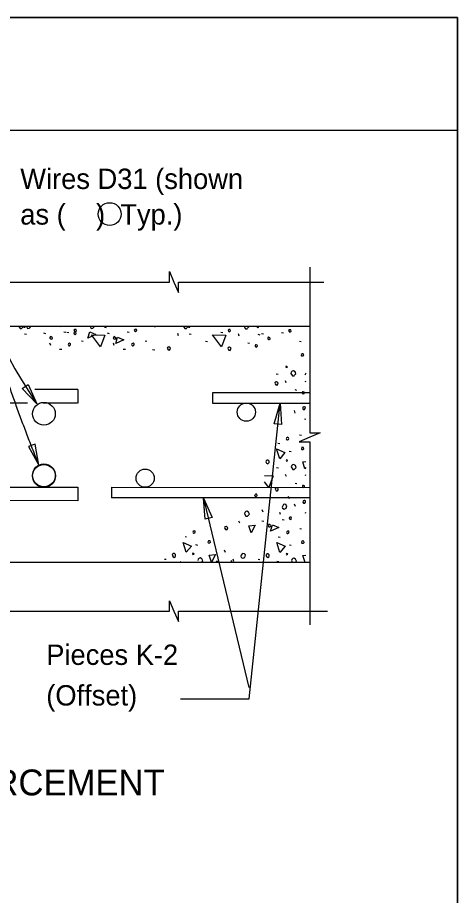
# Model space of a CAD drawing. Extents: x 0 to 20.5, y 0 to 13.
# Drawn here: x 18.352 to 20.525, y 8.632 to 12.973 of the extents above; entities that cross this region are included whole.
import ezdxf

# ---------------------------------------------------------------- set-up
doc = ezdxf.new("R2010")
doc.units = 0
for name, color, linetype in [('ActivePts-ConstElements', 7, 'Continuous'), ('BeamConc', 7, 'Continuous'), ('Dimension', 7, 'Continuous'), ('Miscellaneous', 7, 'Continuous'), ('Miscellaneous1', 7, 'Continuous'), ('Rebar', 7, 'Continuous'), ('Rebar_h', 7, 'Continuous')]:
    doc.layers.add(name, color=color, linetype=linetype)

msp = doc.modelspace()

# ---------------------------------------------------------------- linework, layer by layer
at = {"layer": 'ActivePts-ConstElements'}
msp.add_lwpolyline([(0, 0), (20.5253, 0), (20.5253, 12.9731), (0, 12.9731)], close=True, dxfattribs=at)
at = {"layer": 'BeamConc'}
for p, q in [((19.7956, 11.4449), (16.1478, 11.4449)), ((19.7956, 10.2782), (16.1478, 10.2782))]:
    msp.add_line(p, q, dxfattribs=at)
at = {"layer": 'Dimension'}
for p, q in [((-0.008, 12.4165), (20.5253, 12.4165)), ((19.4966, 9.6606), (19.2748, 10.5821))]:
    msp.add_line(p, q, dxfattribs=at)
for points in [[(19.7956, 11.7379), (19.7956, 10.9199), (19.8473, 10.9199), (19.7956, 10.8974), (19.7439, 10.8749), (19.7956, 10.8749), (19.7956, 9.9704)], [(18.2538, 11.6648), (19.102, 11.6648), (19.102, 11.7165), (19.1245, 11.6648), (19.147, 11.6131), (19.147, 11.6648), (19.8652, 11.6648)], [(19.1573, 9.6044), (19.4966, 9.6044), (19.649, 11.0659)], [(18.1961, 10.0376), (19.102, 10.0376), (19.102, 10.0893), (19.1245, 10.0376), (19.147, 9.986), (19.147, 10.0376), (19.883, 10.0376)]]:
    msp.add_lwpolyline(points, dxfattribs=at)
for points in [[(18.4035, 11.1587), (18.4476, 11.0627), (18.3744, 11.1388)], [(19.6206, 10.9641), (19.649, 11.0659), (19.6557, 10.9605)], [(18.4566, 10.7599), (18.4391, 10.8641), (18.4058, 10.8525)], [(19.2785, 10.4918), (19.2713, 10.5972), (19.3128, 10.5001)]]:
    msp.add_lwpolyline(points, close=True, dxfattribs=at)
for points, degree in [([(18.1627, 11.6549), (18.2484, 11.2789), (18.4566, 10.7599)], 2), ([(18.1631, 11.6533), (18.1786, 11.6093), (18.2222, 11.3932), (18.4476, 11.0627)], 3)]:
    msp.add_open_spline(points, degree=degree, dxfattribs=at)
at = {"layer": 'Miscellaneous'}
for p, q in [((18.5528, 11.4435), (18.5522, 11.4449)), ((18.5687, 11.4423), (18.5677, 11.4449)), ((18.5798, 11.4188), (18.5898, 11.417)), ((18.5957, 11.4176), (18.6058, 11.4158)), ((18.7802, 11.4429), (18.7902, 11.4411)), ((18.8938, 11.4188), (18.9038, 11.417)), ((19.0318, 11.4411), (19.0304, 11.4449)), ((19.3569, 11.4176), (19.3669, 11.4158)), ((18.3866, 11.4093), (18.3961, 11.407)), ((18.4803, 11.4134), (18.4897, 11.4111)), ((18.6676, 11.3746), (18.6765, 11.3728)), ((18.7943, 11.4134), (18.8037, 11.4111)), ((18.9816, 11.3746), (18.9904, 11.3728)), ((19.1478, 11.3993), (19.1437, 11.4105)), ((19.2006, 11.4093), (19.2101, 11.407)), ((19.4475, 11.3981), (19.4433, 11.4093)), ((19.5388, 11.407), (19.5482, 11.4046)), ((19.557, 11.4111), (19.5664, 11.4087)), ((19.6566, 11.4164), (19.6666, 11.4146)), ((18.5156, 11.351), (18.5115, 11.3622)), ((18.5598, 11.3339), (18.5704, 11.3327)), ((18.8296, 11.351), (18.8255, 11.3622)), ((18.8738, 11.3339), (18.8844, 11.3327)), ((19.0188, 11.3315), (19.0294, 11.3304)), ((19.2813, 11.3734), (19.2901, 11.3716)), ((19.4899, 11.3651), (19.4987, 11.3634)), ((19.7444, 11.3722), (19.7532, 11.3704)), ((19.6301, 11.2108), (19.6401, 11.209)), ((19.6796, 11.166), (19.6755, 11.1772)), ((19.7709, 11.1748), (19.776, 11.1736)), ((19.722, 11.133), (19.7309, 11.1312)), ((19.7243, 11.0175), (19.7196, 11.0293)), ((19.7703, 10.9881), (19.776, 10.9873)), ((19.7455, 10.9091), (19.7544, 10.9074)), ((19.6377, 10.8685), (19.6483, 10.8673)), ((19.6937, 10.829), (19.7031, 10.8266)), ((19.6313, 10.7477), (19.6413, 10.7459)), ((19.6808, 10.7029), (19.6766, 10.7141)), ((19.7721, 10.7118), (19.776, 10.7108)), ((19.7232, 10.6699), (19.732, 10.6682)), ((19.6955, 10.5927), (19.6908, 10.6045)), ((19.7255, 10.5545), (19.7208, 10.5662)), ((19.5652, 10.5266), (19.5605, 10.5384)), ((19.6519, 10.5149), (19.6478, 10.5261)), ((19.7715, 10.525), (19.776, 10.5244)), ((19.4498, 10.472), (19.4457, 10.4832)), ((19.5594, 10.4849), (19.5688, 10.4825)), ((19.6589, 10.4902), (19.6689, 10.4885)), ((19.7467, 10.446), (19.7556, 10.4443)), ((19.18, 10.4061), (19.1864, 10.4054)), ((19.6389, 10.4054), (19.6495, 10.4042)), ((19.2318, 10.3671), (19.2412, 10.3647)), ((19.3791, 10.3282), (19.3744, 10.34)), ((19.6949, 10.3659), (19.7043, 10.3635)), ((19.0774, 10.2952), (19.0857, 10.294)), ((19.4209, 10.284), (19.4168, 10.2952)), ((19.5405, 10.294), (19.5488, 10.2929)), ((19.3328, 10.2858), (19.3428, 10.284)), ((19.6324, 10.2846), (19.6425, 10.2829))]:
    msp.add_line(p, q, dxfattribs=at)
for points in [[(18.3581, 11.4449), (18.3644, 11.4347), (18.3721, 11.4353), (18.375, 11.4382), (18.3815, 11.4447), (18.3814, 11.4449)], [(18.3866, 11.4388), (18.3846, 11.4449)], [(18.3898, 11.4449), (18.3866, 11.4388)], [(18.3958, 11.4449), (18.4013, 11.4358), (18.409, 11.4364), (18.412, 11.4394), (18.4174, 11.4449)], [(18.403, 11.444), (18.4027, 11.4449)], [(18.4088, 11.4449), (18.4075, 11.4423)], [(18.6321, 11.4091), (18.6357, 11.4056), (18.6392, 11.408), (18.6416, 11.4115), (18.6404, 11.4174), (18.6374, 11.418), (18.6333, 11.4174), (18.6298, 11.4139), (18.6321, 11.4091)], [(18.6329, 11.4217), (18.6364, 11.4182), (18.6399, 11.4205), (18.6423, 11.4241), (18.6411, 11.4299), (18.6382, 11.4305), (18.6341, 11.4299), (18.6305, 11.4264), (18.6329, 11.4217)], [(18.6988, 11.3881), (18.7082, 11.4187), (18.7394, 11.4064), (18.6988, 11.3881)], [(18.7098, 11.4449), (18.7153, 11.4358), (18.723, 11.4364), (18.7259, 11.4394), (18.7314, 11.4449)], [(18.9309, 11.4229), (18.9345, 11.4193), (18.938, 11.4217), (18.9404, 11.4252), (18.9392, 11.4311), (18.9362, 11.4317), (18.9321, 11.4311), (18.9286, 11.4276), (18.9309, 11.4229)], [(19.1721, 11.4449), (19.1784, 11.4347), (19.1861, 11.4353), (19.189, 11.4382), (19.1955, 11.4447), (19.1954, 11.4449)], [(19.2006, 11.4388), (19.1986, 11.4449)], [(19.2038, 11.4449), (19.2006, 11.4388)], [(19.394, 11.4217), (19.3975, 11.4182), (19.4011, 11.4205), (19.4034, 11.4241), (19.4023, 11.4299), (19.3993, 11.4305), (19.3952, 11.4299), (19.3917, 11.4264), (19.394, 11.4217)], [(19.4711, 11.4449), (19.4781, 11.4335), (19.4858, 11.4341), (19.4887, 11.437), (19.4952, 11.4435), (19.4946, 11.4449)], [(19.5388, 11.4364), (19.536, 11.4449)], [(19.5431, 11.4449), (19.5388, 11.4364)], [(19.6937, 11.4205), (19.6972, 11.417), (19.7008, 11.4193), (19.7031, 11.4229), (19.7019, 11.4288), (19.699, 11.4294), (19.6949, 11.4288), (19.6913, 11.4252), (19.6937, 11.4205)], [(18.5144, 11.384), (18.5186, 11.3834), (18.5227, 11.3851), (18.5239, 11.3887), (18.5221, 11.3916), (18.5186, 11.394), (18.5144, 11.3957), (18.5121, 11.391), (18.5109, 11.3875), (18.5144, 11.384)], [(18.7619, 11.3445), (18.7171, 11.4034), (18.7837, 11.4028), (18.7619, 11.3445)], [(18.8284, 11.384), (18.8326, 11.3834), (18.8367, 11.3851), (18.8379, 11.3887), (18.8361, 11.3916), (18.8326, 11.394), (18.8284, 11.3957), (18.8261, 11.391), (18.8249, 11.3875), (18.8284, 11.384)], [(18.8367, 11.3616), (18.8461, 11.3922), (18.8773, 11.3799), (18.8367, 11.3616)], [(19.3597, 11.3445), (19.3149, 11.4034), (19.3815, 11.4028), (19.3597, 11.3445)], [(19.5912, 11.3816), (19.5953, 11.381), (19.5994, 11.3828), (19.6006, 11.3863), (19.5989, 11.3893), (19.5953, 11.3916), (19.5912, 11.3934), (19.5888, 11.3887), (19.5877, 11.3851), (19.5912, 11.3816)], [(18.6052, 11.3498), (18.6075, 11.3498), (18.6122, 11.3522), (18.614, 11.3575), (18.6134, 11.3604), (18.6087, 11.3628), (18.6028, 11.3592), (18.6016, 11.3557), (18.6028, 11.3522), (18.6052, 11.3498)], [(18.9191, 11.3498), (18.9215, 11.3498), (18.9262, 11.3522), (18.928, 11.3575), (18.9274, 11.3604), (18.9227, 11.3628), (18.9168, 11.3592), (18.9156, 11.3557), (18.9168, 11.3522), (18.9191, 11.3498)], [(19.093, 11.3351), (19.0959, 11.3298), (19.103, 11.3286), (19.1059, 11.3339), (19.1071, 11.3386), (19.1042, 11.3416), (19.0989, 11.3445), (19.0936, 11.3427), (19.0918, 11.3374), (19.093, 11.3351)], [(19.3927, 11.3339), (19.3956, 11.3286), (19.4027, 11.3274), (19.4056, 11.3327), (19.4068, 11.3374), (19.4039, 11.3404), (19.3985, 11.3433), (19.3932, 11.3416), (19.3915, 11.3363), (19.3927, 11.3339)], [(19.5258, 11.3457), (19.5323, 11.3439), (19.5364, 11.3469), (19.537, 11.351), (19.5358, 11.3522), (19.5311, 11.3545), (19.527, 11.3539), (19.5264, 11.3498), (19.5258, 11.3457)], [(19.755, 11.3003), (19.762, 11.3003), (19.7656, 11.3038), (19.7638, 11.3103), (19.7562, 11.3109), (19.755, 11.3074), (19.7532, 11.3044), (19.755, 11.3003), (19.7538, 11.3015)], [(19.679, 11.242), (19.6855, 11.245), (19.6831, 11.2473), (19.679, 11.2491), (19.6772, 11.245), (19.679, 11.242)], [(19.7026, 11.2137), (19.7102, 11.2014), (19.7179, 11.2019), (19.7208, 11.2049), (19.7273, 11.2114), (19.7232, 11.2214), (19.7149, 11.2261), (19.709, 11.2237), (19.7043, 11.219), (19.7026, 11.2137)], [(19.776, 11.2142), (19.7709, 11.2043)], [(19.6248, 11.1619), (19.6277, 11.1566), (19.6348, 11.1554), (19.6377, 11.1608), (19.6389, 11.1655), (19.636, 11.1684), (19.6307, 11.1714), (19.6254, 11.1696), (19.6236, 11.1643), (19.6248, 11.1619)], [(19.758, 11.1136), (19.7644, 11.1118), (19.7686, 11.1147), (19.7692, 11.1189), (19.768, 11.12), (19.7633, 11.1224), (19.7591, 11.1218), (19.7585, 11.1177), (19.758, 11.1136)], [(19.7609, 11.0399), (19.7638, 11.0346), (19.7703, 11.0352), (19.7732, 11.0393), (19.7738, 11.0458), (19.7697, 11.0476), (19.7668, 11.0482), (19.7632, 11.047), (19.762, 11.0458), (19.7609, 11.0399)], [(19.6831, 10.8844), (19.6854, 10.8844), (19.6902, 10.8867), (19.6919, 10.892), (19.6913, 10.895), (19.6866, 10.8973), (19.6807, 10.8938), (19.6795, 10.8903), (19.6807, 10.8867), (19.6831, 10.8844)], [(19.6472, 10.7907), (19.6313, 10.8396), (19.6731, 10.8214), (19.6472, 10.7907)], [(19.7562, 10.8372), (19.7632, 10.8372), (19.7668, 10.8408), (19.765, 10.8472), (19.7573, 10.8478), (19.7562, 10.8443), (19.7544, 10.8414), (19.7562, 10.8372), (19.755, 10.8384)], [(19.5782, 10.776), (19.5818, 10.7689), (19.5877, 10.7654), (19.5924, 10.7689), (19.5947, 10.7725), (19.5947, 10.7795), (19.5894, 10.7848), (19.5829, 10.7842), (19.58, 10.7813), (19.5782, 10.776)], [(19.6802, 10.7789), (19.6867, 10.7819), (19.6843, 10.7842), (19.6802, 10.786), (19.6784, 10.7819), (19.6802, 10.7789)], [(19.7721, 10.7412), (19.7609, 10.7759), (19.776, 10.7779)], [(19.7037, 10.7506), (19.7114, 10.7383), (19.7191, 10.7389), (19.722, 10.7418), (19.7285, 10.7483), (19.7244, 10.7583), (19.7161, 10.763), (19.7102, 10.7607), (19.7055, 10.756), (19.7037, 10.7506)], [(19.776, 10.7488), (19.7721, 10.7412)], [(19.572, 10.708), (19.6148, 10.7076), (19.593, 10.6493)], [(19.593, 10.6493), (19.5719, 10.677)], [(19.626, 10.6387), (19.6289, 10.6334), (19.636, 10.6322), (19.6389, 10.6375), (19.6401, 10.6422), (19.6372, 10.6452), (19.6319, 10.6481), (19.6266, 10.6463), (19.6248, 10.641), (19.626, 10.6387)], [(19.7591, 10.6505), (19.7656, 10.6487), (19.7697, 10.6517), (19.7703, 10.6558), (19.7692, 10.657), (19.7644, 10.6593), (19.7603, 10.6587), (19.7597, 10.6546), (19.7591, 10.6505)], [(19.5255, 10.6141), (19.5252, 10.6134), (19.5234, 10.6104), (19.5252, 10.6063), (19.524, 10.6075)], [(19.5252, 10.6063), (19.5323, 10.6063), (19.5358, 10.6098), (19.534, 10.6163), (19.5276, 10.6168)], [(19.6613, 10.5468), (19.669, 10.5426), (19.679, 10.5468), (19.6831, 10.5591), (19.6772, 10.565), (19.6696, 10.5668), (19.666, 10.5644), (19.6619, 10.558), (19.659, 10.5527), (19.6613, 10.5468)], [(19.762, 10.5769), (19.765, 10.5716), (19.7715, 10.5721), (19.7744, 10.5763), (19.775, 10.5827), (19.7709, 10.5845), (19.7679, 10.5851), (19.7644, 10.5839), (19.7632, 10.5827), (19.762, 10.5769)], [(19.4728, 10.5197), (19.4805, 10.5073), (19.4881, 10.5079), (19.4911, 10.5109), (19.4975, 10.5173), (19.4934, 10.5274), (19.4852, 10.5321), (19.4793, 10.5297), (19.4746, 10.525), (19.4728, 10.5197)], [(19.5055, 10.4246), (19.4943, 10.4593), (19.5255, 10.4635), (19.5055, 10.4246)], [(19.5936, 10.4554), (19.5977, 10.4548), (19.6018, 10.4566), (19.603, 10.4601), (19.6012, 10.4631), (19.5977, 10.4654), (19.5936, 10.4672), (19.5912, 10.4625), (19.59, 10.459), (19.5936, 10.4554)], [(19.6018, 10.4331), (19.6112, 10.4637), (19.6424, 10.4513), (19.6018, 10.4331)], [(19.696, 10.4944), (19.6996, 10.4908), (19.7031, 10.4932), (19.7055, 10.4967), (19.7043, 10.5026), (19.7014, 10.5032), (19.6972, 10.5026), (19.6937, 10.4991), (19.696, 10.4944)], [(19.2212, 10.4225), (19.2235, 10.4225), (19.2283, 10.4248), (19.23, 10.4301), (19.2294, 10.4331), (19.2247, 10.4354), (19.2188, 10.4319), (19.2176, 10.4284), (19.2188, 10.4248), (19.2212, 10.4225)], [(19.3761, 10.4466), (19.379, 10.4413), (19.3861, 10.4401), (19.389, 10.4454), (19.3902, 10.4501), (19.3872, 10.4531), (19.3819, 10.456), (19.3766, 10.4542), (19.3749, 10.4489), (19.3761, 10.4466)], [(19.6843, 10.4213), (19.6866, 10.4213), (19.6913, 10.4236), (19.6931, 10.429), (19.6925, 10.4319), (19.6878, 10.4343), (19.6819, 10.4307), (19.6807, 10.4272), (19.6819, 10.4236), (19.6843, 10.4213)], [(19.1853, 10.3288), (19.1694, 10.3777), (19.2112, 10.3595), (19.1853, 10.3288)], [(19.2942, 10.3753), (19.3013, 10.3753), (19.3049, 10.3789), (19.3031, 10.3853), (19.2954, 10.3859), (19.2942, 10.3824), (19.2925, 10.3795), (19.2942, 10.3753), (19.2931, 10.3765)], [(19.6484, 10.3276), (19.6324, 10.3765), (19.6743, 10.3583), (19.6484, 10.3276)], [(19.7573, 10.3742), (19.7644, 10.3742), (19.7679, 10.3777), (19.7662, 10.3842), (19.7585, 10.3848), (19.7573, 10.3812), (19.7556, 10.3783), (19.7573, 10.3742), (19.7562, 10.3753)], [(19.1163, 10.3141), (19.1199, 10.307), (19.1258, 10.3035), (19.1305, 10.307), (19.1328, 10.3105), (19.1328, 10.3176), (19.1275, 10.3229), (19.121, 10.3223), (19.1181, 10.3194), (19.1163, 10.3141)], [(19.2183, 10.317), (19.2248, 10.32), (19.2224, 10.3223), (19.2183, 10.3241), (19.2165, 10.32), (19.2183, 10.317)], [(19.2595, 10.2793), (19.2601, 10.2799), (19.2666, 10.2864), (19.2625, 10.2964), (19.2542, 10.3011), (19.2483, 10.2988), (19.2436, 10.294), (19.2418, 10.2887)], [(19.3102, 10.2793), (19.299, 10.314), (19.3302, 10.3182), (19.3102, 10.2793)], [(19.4566, 10.303), (19.4643, 10.2989), (19.4743, 10.303), (19.4784, 10.3154), (19.4725, 10.3212), (19.4649, 10.323), (19.4613, 10.3207), (19.4572, 10.3142), (19.4543, 10.3089), (19.4566, 10.303)], [(19.5794, 10.3129), (19.5829, 10.3058), (19.5888, 10.3023), (19.5936, 10.3058), (19.5959, 10.3094), (19.5959, 10.3164), (19.5906, 10.3217), (19.5841, 10.3212), (19.5812, 10.3182), (19.5794, 10.3129)], [(19.6814, 10.3159), (19.6878, 10.3188), (19.6855, 10.3212), (19.6814, 10.3229), (19.6796, 10.3188), (19.6814, 10.3159)], [(19.7228, 10.2783), (19.7232, 10.2787), (19.7297, 10.2852), (19.7255, 10.2952), (19.7173, 10.2999), (19.7114, 10.2976), (19.7067, 10.2929), (19.7049, 10.2876)], [(19.7732, 10.2782), (19.762, 10.3129), (19.776, 10.3147)], [(19.1582, 10.2834), (19.1555, 10.2782)], [(19.4052, 10.2887), (19.4111, 10.2793)], [(19.7049, 10.2876), (19.7106, 10.2783)]]:
    msp.add_lwpolyline(points, dxfattribs=at)
at = {"layer": 'Miscellaneous1'}
msp.add_lwpolyline([(0, 12.9731), (20.5253, 12.9731), (20.5253, 0), (0, 0)], close=True, dxfattribs=at)
at = {"layer": 'Rebar'}
for centre, radius in [((18.8069, 12.0012), 0.0563), ((18.4821, 11.0136), 0.0563), ((19.4822, 11.0218), 0.045), ((18.4821, 10.7094), 0.0563), ((18.4822, 10.7064), 0.0563), ((18.9822, 10.6951), 0.045)]:
    msp.add_circle(centre, radius, dxfattribs=at)
at = {"layer": 'Rebar_h'}
for p, q in [((18.6489, 11.1335), (18.6489, 11.0668)), ((19.3155, 11.1179), (19.3155, 11.0662)), ((17.648, 11.0684), (18.4002, 11.0676)), ((18.4784, 11.0675), (18.6488, 11.0674)), ((19.3155, 11.0662), (19.7949, 11.0657)), ((16.3155, 10.6532), (18.6489, 10.6507)), ((18.6489, 10.6502), (18.6489, 10.5835)), ((18.8155, 10.65), (18.8155, 10.5983)), ((18.8155, 10.65), (19.7959, 10.6489)), ((19.7958, 10.5973), (18.8155, 10.5983)), ((18.6488, 10.584), (16.3155, 10.5865))]:
    msp.add_line(p, q, dxfattribs=at)
for points in [[(18.6489, 11.134), (18.4372, 11.1343)], [(19.795, 11.1174), (19.3155, 11.1179)]]:
    msp.add_lwpolyline(points, dxfattribs=at)

# ---------------------------------------------------------------- texts
at = {"layer": 'Dimension'}
for s, height, p in [('Wires D31 (shown ', 0.1008, (18.3652, 12.1253)), ('as (    )  Typ.)', 0.1008, (18.3652, 11.9493)), ('Pieces K-2 ', 0.1008, (18.4937, 9.7718)), ('(Offset)', 0.1008, (18.4937, 9.571)), ('FOR WELDED WIRE REINFORCEMENT', 0.128, (15.9028, 9.1266))]:
    msp.add_text(s, height=height, dxfattribs=at).set_placement(p)

doc.saveas('drawing.dxf')
